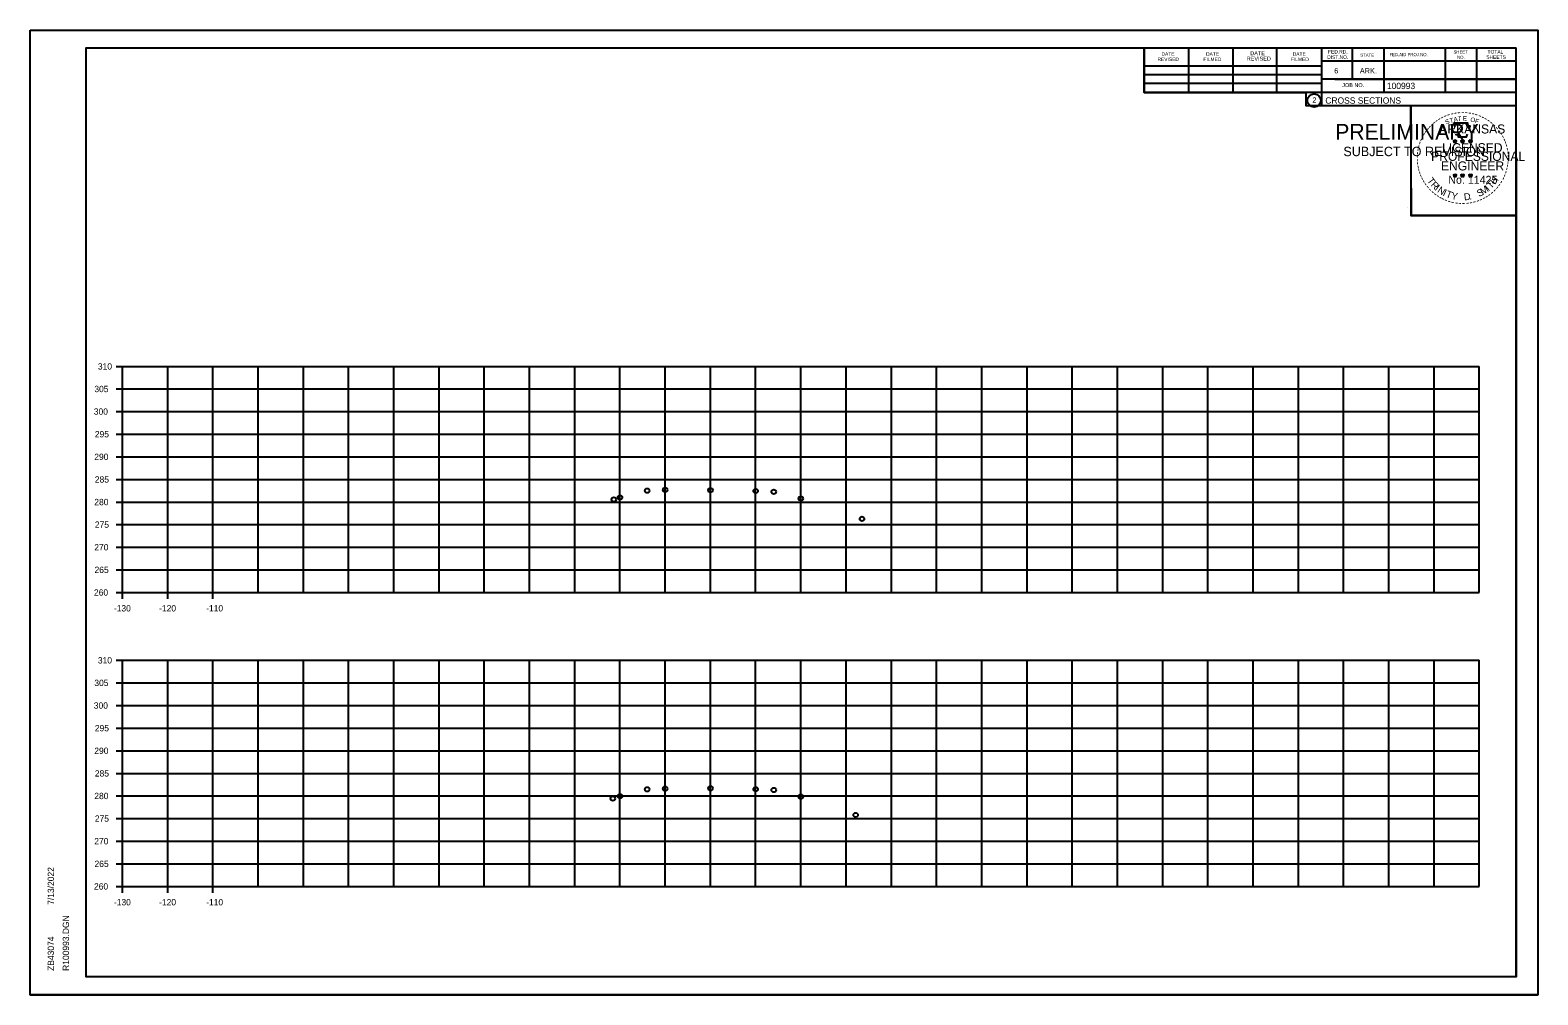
# Model space of a CAD drawing. Extents: x 4667 to 1632277, y -2100 to 724501.
# Drawn here: x 5969.1 to 6302.5, y -43.7 to 169.6 of the extents above; entities that cross this region are included whole.
import ezdxf

# ---------------------------------------------------------------- set-up
doc = ezdxf.new("R2010")
doc.units = 0
for name, color, linetype in [('R_Axis', 7, 'Continuous'), ('R_Axis Annot', 7, 'Continuous'), ('R_Grid', 7, 'Continuous'), ('R_No Plot', 7, 'Continuous')]:
    doc.layers.add(name, color=color, linetype=linetype)

msp = doc.modelspace()

# ---------------------------------------------------------------- linework, layer by layer
at = {"layer": 'R_Axis'}
for p, q in [((5988.12, 95.26), (5989.52, 95.26)), ((5989.52, 45.26), (5989.52, 95.26)), ((5988.12, 90.26), (5989.52, 90.26)), ((5988.12, 85.26), (5989.52, 85.26)), ((5988.12, 80.26), (5989.52, 80.26)), ((5988.12, 75.26), (5989.52, 75.26)), ((5988.12, 70.26), (5989.52, 70.26)), ((5988.12, 65.26), (5989.52, 65.26)), ((5988.12, 60.26), (5989.52, 60.26)), ((5988.12, 55.26), (5989.52, 55.26)), ((5988.12, 50.26), (5989.52, 50.26)), ((5988.12, 45.26), (5989.52, 45.26)), ((5989.52, 43.86), (5989.52, 45.26)), ((5999.52, 43.86), (5999.52, 45.26)), ((6009.52, 43.86), (6009.52, 45.26)), ((5988.12, 30.26), (5989.52, 30.26)), ((5989.52, -19.74), (5989.52, 30.26)), ((5988.12, 25.26), (5989.52, 25.26)), ((5988.12, 20.26), (5989.52, 20.26)), ((5988.12, 15.26), (5989.52, 15.26)), ((5988.12, 10.26), (5989.52, 10.26)), ((5988.12, 5.26), (5989.52, 5.26)), ((5988.12, 0.26), (5989.52, 0.26)), ((5988.12, -4.74), (5989.52, -4.74)), ((5988.12, -9.74), (5989.52, -9.74)), ((5988.12, -14.74), (5989.52, -14.74)), ((5988.12, -19.74), (5989.52, -19.74)), ((5989.52, -21.14), (5989.52, -19.74)), ((5999.52, -21.14), (5999.52, -19.74)), ((6009.52, -21.14), (6009.52, -19.74))]:
    msp.add_line(p, q, dxfattribs=at)
at = {"layer": 'R_Grid'}
for p, q in [((5989.52, 95.26), (6289.52, 95.26)), ((5989.52, 45.26), (5989.52, 95.26)), ((5999.52, 45.26), (5999.52, 95.26)), ((6009.52, 45.26), (6009.52, 95.26)), ((6019.52, 45.26), (6019.52, 95.26)), ((6029.52, 45.26), (6029.52, 95.26)), ((6039.52, 45.26), (6039.52, 95.26)), ((6049.52, 45.26), (6049.52, 95.26)), ((6059.52, 45.26), (6059.52, 95.26)), ((6069.52, 45.26), (6069.52, 95.26)), ((6079.52, 45.26), (6079.52, 95.26)), ((6089.52, 45.26), (6089.52, 95.26)), ((6099.52, 45.26), (6099.52, 95.26)), ((6109.52, 45.26), (6109.52, 95.26)), ((6119.52, 45.26), (6119.52, 95.26)), ((6129.52, 45.26), (6129.52, 95.26)), ((6139.52, 45.26), (6139.52, 95.26)), ((6149.52, 45.26), (6149.52, 95.26)), ((6159.52, 45.26), (6159.52, 95.26)), ((6169.52, 45.26), (6169.52, 95.26)), ((6179.52, 45.26), (6179.52, 95.26)), ((6189.52, 45.26), (6189.52, 95.26)), ((6199.52, 45.26), (6199.52, 95.26)), ((6209.52, 45.26), (6209.52, 95.26)), ((6219.52, 45.26), (6219.52, 95.26)), ((6229.52, 45.26), (6229.52, 95.26)), ((6239.52, 45.26), (6239.52, 95.26)), ((6249.52, 45.26), (6249.52, 95.26)), ((6259.52, 45.26), (6259.52, 95.26)), ((6269.52, 45.26), (6269.52, 95.26)), ((6279.52, 45.26), (6279.52, 95.26)), ((6289.52, 45.26), (6289.52, 95.26)), ((5989.52, 90.26), (6289.52, 90.26)), ((5989.52, 85.26), (6289.52, 85.26)), ((5989.52, 80.26), (6289.52, 80.26)), ((5989.52, 75.26), (6289.52, 75.26)), ((5989.52, 70.26), (6289.52, 70.26)), ((5989.52, 65.26), (6289.52, 65.26)), ((5989.52, 60.26), (6289.52, 60.26)), ((5989.52, 55.26), (6289.52, 55.26)), ((5989.52, 50.26), (6289.52, 50.26)), ((5989.52, 45.26), (6289.52, 45.26)), ((5989.52, 30.26), (6289.52, 30.26)), ((5989.52, -19.74), (5989.52, 30.26)), ((5999.52, -19.74), (5999.52, 30.26)), ((6009.52, -19.74), (6009.52, 30.26)), ((6019.52, -19.74), (6019.52, 30.26)), ((6029.52, -19.74), (6029.52, 30.26)), ((6039.52, -19.74), (6039.52, 30.26)), ((6049.52, -19.74), (6049.52, 30.26)), ((6059.52, -19.74), (6059.52, 30.26)), ((6069.52, -19.74), (6069.52, 30.26)), ((6079.52, -19.74), (6079.52, 30.26)), ((6089.52, -19.74), (6089.52, 30.26)), ((6099.52, -19.74), (6099.52, 30.26)), ((6109.52, -19.74), (6109.52, 30.26)), ((6119.52, -19.74), (6119.52, 30.26)), ((6129.52, -19.74), (6129.52, 30.26)), ((6139.52, -19.74), (6139.52, 30.26)), ((6149.52, -19.74), (6149.52, 30.26)), ((6159.52, -19.74), (6159.52, 30.26)), ((6169.52, -19.74), (6169.52, 30.26)), ((6179.52, -19.74), (6179.52, 30.26)), ((6189.52, -19.74), (6189.52, 30.26)), ((6199.52, -19.74), (6199.52, 30.26)), ((6209.52, -19.74), (6209.52, 30.26)), ((6219.52, -19.74), (6219.52, 30.26)), ((6229.52, -19.74), (6229.52, 30.26)), ((6239.52, -19.74), (6239.52, 30.26)), ((6249.52, -19.74), (6249.52, 30.26)), ((6259.52, -19.74), (6259.52, 30.26)), ((6269.52, -19.74), (6269.52, 30.26)), ((6279.52, -19.74), (6279.52, 30.26)), ((6289.52, -19.74), (6289.52, 30.26)), ((5989.52, 25.26), (6289.52, 25.26)), ((5989.52, 20.26), (6289.52, 20.26)), ((5989.52, 15.26), (6289.52, 15.26)), ((5989.52, 10.26), (6289.52, 10.26)), ((5989.52, 5.26), (6289.52, 5.26)), ((5989.52, 0.26), (6289.52, 0.26)), ((5989.52, -4.74), (6289.52, -4.74)), ((5989.52, -9.74), (6289.52, -9.74)), ((5989.52, -14.74), (6289.52, -14.74)), ((5989.52, -19.74), (6289.52, -19.74))]:
    msp.add_line(p, q, dxfattribs=at)
at = {"layer": 'R_No Plot'}
for p, q in [((5969.12, 169.61), (6302.46, 169.61)), ((5981.52, 165.72), (6297.7, 165.72)), ((5981.52, -39.74), (5981.52, 165.72)), ((6134.04, 165.46), (6134.04, 165.46)), ((6134.04, 165.46), (6134.04, 165.46)), ((6215.44, 155.84), (6215.44, 165.72)), ((6225.3, 155.84), (6225.3, 165.52)), ((6235.06, 155.84), (6235.06, 165.52)), ((6244.74, 155.84), (6244.74, 165.52)), ((6254.6, 165.72), (6254.6, 152.92)), ((6261.44, 165.72), (6261.44, 158.78)), ((6268.38, 165.72), (6268.38, 155.84)), ((6281.96, 165.72), (6281.96, 155.84)), ((6288.9, 165.72), (6288.9, 155.84)), ((6297.7, -39.74), (6297.7, 165.72)), ((6215.44, 161.7), (6254.6, 161.7)), ((6297.7, 162.78), (6254.6, 162.78)), ((6297.7, 162.8), (6297.7, 162.8)), ((6215.44, 159.84), (6254.6, 159.84)), ((6215.44, 155.84), (6215.44, 157.9)), ((6215.44, 157.9), (6254.6, 157.9)), ((6297.7, 158.78), (6254.6, 158.78)), ((6257.56, 158.78), (6297.7, 158.78)), ((6297.7, 155.84), (6215.44, 155.84)), ((6254.6, 152.92), (6297.7, 152.92)), ((6283.79, 145.17), (6284.14, 145.06)), ((6283.79, 145.17), (6284.04, 145.13)), ((6283.79, 145.17), (6284.03, 145.05)), ((6283.92, 144.77), (6284.14, 145.06)), ((6283.92, 144.77), (6284.05, 145.01)), ((6283.92, 144.77), (6284.14, 144.98)), ((6284.14, 145.43), (6284.1, 145.18)), ((6284.14, 145.06), (6284.14, 145.43)), ((6284.14, 145.43), (6284.19, 145.18)), ((6284.49, 145.17), (6284.14, 145.06)), ((6284.35, 144.77), (6284.14, 145.06)), ((6284.35, 144.77), (6284.14, 144.98)), ((6284.49, 145.17), (6284.2, 145.13)), ((6284.35, 144.77), (6284.21, 145.06)), ((6284.49, 145.17), (6284.28, 145.07)), ((6285.46, 145.17), (6285.81, 145.06)), ((6285.46, 145.17), (6285.71, 145.13)), ((6285.46, 145.17), (6285.7, 145.05)), ((6285.59, 144.77), (6285.81, 145.06)), ((6285.59, 144.77), (6285.72, 145.01)), ((6285.59, 144.77), (6285.81, 144.98)), ((6285.81, 145.43), (6285.77, 145.18)), ((6285.81, 145.06), (6285.81, 145.43)), ((6285.81, 145.43), (6285.86, 145.18)), ((6286.16, 145.17), (6285.81, 145.06)), ((6286.02, 144.77), (6285.81, 145.06)), ((6286.02, 144.77), (6285.81, 144.98)), ((6286.16, 145.17), (6285.87, 145.13)), ((6286.02, 144.77), (6285.88, 145.06)), ((6286.16, 145.17), (6285.95, 145.07)), ((6287.22, 145.16), (6287.57, 145.05)), ((6287.22, 145.16), (6287.48, 145.12)), ((6287.22, 145.16), (6287.46, 145.04)), ((6287.36, 144.75), (6287.57, 145.05)), ((6287.36, 144.75), (6287.48, 145)), ((6287.36, 144.75), (6287.57, 144.97)), ((6287.57, 145.42), (6287.53, 145.16)), ((6287.57, 145.05), (6287.57, 145.42)), ((6287.57, 145.42), (6287.62, 145.17)), ((6287.92, 145.16), (6287.57, 145.05)), ((6287.79, 144.75), (6287.57, 145.05)), ((6287.79, 144.75), (6287.57, 144.97)), ((6287.92, 145.16), (6287.63, 145.11)), ((6287.79, 144.75), (6287.65, 145.05)), ((6287.92, 145.16), (6287.72, 145.06)), ((6283.79, 137.6), (6284.13, 137.49)), ((6283.79, 137.6), (6284.04, 137.56)), ((6283.79, 137.6), (6284.02, 137.48)), ((6283.92, 137.19), (6284.13, 137.49)), ((6283.92, 137.19), (6284.04, 137.44)), ((6283.92, 137.19), (6284.13, 137.41)), ((6284.13, 137.86), (6284.09, 137.6)), ((6284.13, 137.49), (6284.13, 137.86)), ((6284.13, 137.86), (6284.18, 137.61)), ((6284.48, 137.6), (6284.13, 137.49)), ((6284.35, 137.19), (6284.13, 137.49)), ((6284.35, 137.19), (6284.13, 137.41)), ((6284.48, 137.6), (6284.2, 137.55)), ((6284.35, 137.19), (6284.21, 137.48)), ((6284.48, 137.6), (6284.28, 137.5)), ((6285.45, 137.6), (6285.8, 137.49)), ((6285.45, 137.6), (6285.71, 137.56)), ((6285.45, 137.6), (6285.69, 137.48)), ((6285.59, 137.19), (6285.8, 137.49)), ((6285.59, 137.19), (6285.71, 137.44)), ((6285.59, 137.19), (6285.8, 137.41)), ((6285.8, 137.86), (6285.76, 137.6)), ((6285.8, 137.49), (6285.8, 137.86)), ((6285.8, 137.86), (6285.85, 137.61)), ((6286.15, 137.6), (6285.8, 137.49)), ((6286.02, 137.19), (6285.8, 137.49)), ((6286.02, 137.19), (6285.8, 137.41)), ((6286.15, 137.6), (6285.86, 137.55)), ((6286.02, 137.19), (6285.88, 137.48)), ((6286.15, 137.6), (6285.95, 137.5)), ((6287.22, 137.59), (6287.57, 137.48)), ((6287.22, 137.59), (6287.47, 137.55)), ((6287.22, 137.59), (6287.46, 137.47)), ((6287.35, 137.18), (6287.57, 137.48)), ((6287.35, 137.18), (6287.48, 137.43)), ((6287.35, 137.18), (6287.57, 137.4)), ((6287.57, 137.85), (6287.53, 137.59)), ((6287.57, 137.48), (6287.57, 137.85)), ((6287.57, 137.85), (6287.62, 137.6)), ((6287.92, 137.59), (6287.57, 137.48)), ((6287.78, 137.18), (6287.57, 137.48)), ((6287.78, 137.18), (6287.57, 137.4)), ((6287.92, 137.59), (6287.63, 137.54)), ((6287.78, 137.18), (6287.65, 137.47)), ((6287.92, 137.59), (6287.71, 137.49)), ((6273.74, 130.46), (6273.74, 130.46)), ((5981.52, -39.74), (5981.52, -39.74)), ((6297.7, -39.74), (5981.52, -39.74)), ((5969.12, -43.72), (6302.46, -43.72))]:
    msp.add_line(p, q, dxfattribs=at)
for points in [[(5969.12, 169.61), (6302.46, 169.61), (6302.46, -43.72), (5969.12, -43.72)], [(6215.44, 165.72), (6215.44, 155.84), (6251.18, 155.84), (6251.18, 152.92), (6274.38, 152.92), (6274.38, 128.59), (6297.7, 128.59), (6297.7, -39.74), (5981.52, -39.74), (5981.52, 165.72)], [(6274.38, 152.92), (6297.58, 152.92), (6297.7, 128.59), (6274.5, 128.59)]]:
    msp.add_lwpolyline(points, close=True, dxfattribs=at)
for points in [[(6283.83, 149.05), (6284.1, 148.23)], [(6287.34, 148.13), (6287.48, 148.41), (6286.8, 148.39), (6286.95, 149.05), (6283.83, 149.05)], [(6284.14, 145.43), (6284.35, 144.77), (6283.79, 145.17), (6284.49, 145.17), (6283.92, 144.77), (6284.14, 145.43)], [(6284.32, 146.63), (6284.32, 146.54), (6284.89, 146.52), (6284.83, 146.05), (6286.7, 146.05), (6286.9, 146.59)], [(6285.81, 145.43), (6286.02, 144.77), (6285.46, 145.17), (6286.16, 145.17), (6285.59, 144.77), (6285.81, 145.43)], [(6287.57, 145.42), (6287.79, 144.75), (6287.22, 145.16), (6287.92, 145.16), (6287.36, 144.75), (6287.57, 145.42)], [(6284.13, 137.86), (6284.35, 137.19), (6283.79, 137.6), (6284.48, 137.6), (6283.92, 137.19), (6284.13, 137.86)], [(6285.8, 137.86), (6286.02, 137.19), (6285.45, 137.6), (6286.15, 137.6), (6285.59, 137.19), (6285.8, 137.86)], [(6287.57, 137.85), (6287.78, 137.18), (6287.22, 137.59), (6287.92, 137.59), (6287.35, 137.18), (6287.57, 137.85)]]:
    msp.add_lwpolyline(points, dxfattribs=at)
for centre, radius in [((6252.99, 154.06), 1.47), ((6284.14, 145.06), 0.172), ((6284.14, 145.06), 0.145), ((6284.14, 145.06), 0.116), ((6284.14, 145.06), 0.0991), ((6284.14, 145.06), 0.0747), ((6284.14, 145.06), 0.0495), ((6284.14, 145.06), 0.0296), ((6285.81, 145.06), 0.172), ((6285.81, 145.06), 0.145), ((6285.81, 145.06), 0.116), ((6285.81, 145.06), 0.0991), ((6285.81, 145.06), 0.0747), ((6285.81, 145.06), 0.0495), ((6285.81, 145.06), 0.0296), ((6287.57, 145.05), 0.172), ((6287.57, 145.05), 0.145), ((6287.57, 145.05), 0.116), ((6287.57, 145.05), 0.0991), ((6287.57, 145.05), 0.0747), ((6287.57, 145.05), 0.0495), ((6287.57, 145.05), 0.0296), ((6284.13, 137.49), 0.172), ((6284.13, 137.49), 0.145), ((6284.13, 137.49), 0.116), ((6284.13, 137.49), 0.0991), ((6284.13, 137.49), 0.0747), ((6284.13, 137.49), 0.0495), ((6284.13, 137.49), 0.0296), ((6285.8, 137.49), 0.172), ((6285.8, 137.49), 0.145), ((6285.8, 137.49), 0.116), ((6285.8, 137.49), 0.0991), ((6285.8, 137.49), 0.0747), ((6285.8, 137.49), 0.0495), ((6285.8, 137.49), 0.0296), ((6287.57, 137.48), 0.172), ((6287.57, 137.48), 0.145), ((6287.57, 137.48), 0.116), ((6287.57, 137.48), 0.0991), ((6287.57, 137.48), 0.0747), ((6287.57, 137.48), 0.0495), ((6287.57, 137.48), 0.0296), ((6099.52, 66.28), 0.5), ((6105.52, 67.78), 0.5), ((6109.52, 67.94), 0.5), ((6119.52, 67.89), 0.5), ((6129.52, 67.69), 0.5), ((6133.52, 67.53), 0.5), ((6098.17, 65.83), 0.5), ((6139.52, 66.03), 0.5), ((6153.02, 61.53), 0.5), ((6097.95, -0.3), 0.5), ((6099.52, 0.22), 0.5), ((6105.52, 1.72), 0.5), ((6109.52, 1.88), 0.5), ((6119.52, 1.95), 0.5), ((6129.52, 1.75), 0.5), ((6133.52, 1.59), 0.5), ((6139.52, 0.09), 0.5), ((6151.62, -3.95), 0.5)]:
    msp.add_circle(centre, radius, dxfattribs=at)

# ---------------------------------------------------------------- texts
at = {"layer": 'R_Axis Annot'}
for s, p in [('310', (5984.09, 94.56)), ('305', (5983.31, 89.56)), ('300', (5983.19, 84.56)), ('295', (5983.42, 79.56)), ('290', (5983.3, 74.56)), ('285', (5983.42, 69.56)), ('280', (5983.3, 64.56)), ('275', (5983.42, 59.56)), ('270', (5983.3, 54.56)), ('265', (5983.35, 49.56)), ('260', (5983.23, 44.56)), ('-130', (5987.63, 41.06)), ('-120', (5997.63, 41.06)), ('-110', (6008.03, 41.06)), ('310', (5984.09, 29.56)), ('305', (5983.31, 24.56)), ('300', (5983.19, 19.56)), ('295', (5983.42, 14.56)), ('290', (5983.3, 9.56)), ('285', (5983.42, 4.56)), ('280', (5983.3, -0.44)), ('275', (5983.42, -5.44)), ('270', (5983.3, -10.44)), ('265', (5983.35, -15.44)), ('260', (5983.23, -20.44)), ('-130', (5987.63, -23.94)), ('-120', (5997.63, -23.94)), ('-110', (6008.03, -23.94))]:
    msp.add_text(s, height=1.4, dxfattribs=at).set_placement(p)
at = {"layer": 'R_No Plot'}
for s, height, rotation, p in [('REVISED', 0.782, 360, (6218.36, 162.78)), ('DATE', 0.782, 360, (6219.24, 163.96)), ('FILMED', 0.782, 360, (6228.52, 162.78)), ('DATE', 0.782, 360, (6229.1, 163.96)), ('REVISED', 0.879, 360, (6238.1, 162.88)), ('DATE', 0.879, 360, (6238.88, 164.06)), ('FILMED', 0.782, 360, (6247.86, 162.78)), ('DATE', 0.782, 360, (6248.26, 163.96)), ('DIST.NO.', 0.782, 360, (6255.88, 163.26)), ('FED.RD.', 0.782, 360, (6256.08, 164.44)), ('STATE', 0.684, 360, (6263.2, 163.76)), ('FED.AID PROJ.NO.', 0.684, 360, (6269.66, 163.86)), ('SHEET', 0.684, 360, (6283.82, 164.44)), ('NO.', 0.684, 360, (6284.6, 163.26)), ('SHEETS', 0.782, 360, (6291.06, 163.26)), ('TOTAL', 0.782, 360, (6291.34, 164.44)), ('6', 1.17, 360, (6257.44, 160.04)), ('ARK.', 1.172, 360, (6263.1, 160.04)), ('JOB NO.', 0.879, 360, (6259.2, 157.02)), ('100993', 1.4, 360, (6269.08, 156.58)), ('2', 1.17, 360, (6252.61, 153.57)), ('CROSS SECTIONS', 1.4, 360, (6255.47, 153.35)), ('-', 1.6, 34.0636, (6280.71, 149.22)), ('-', 1.6, 28.7918, (6281.31, 149.59)), ('-', 1.6, 24.3072, (6281.94, 149.91)), ('-', 1.6, 19.1761, (6282.58, 150.18)), ('T', 1, 16.4036, (6283.1, 149.06)), ('-', 1.6, 13.6301, (6283.33, 150.42)), ('A', 1, 11.2132, (6283.92, 149.31)), ('-', 1.6, 10.2193, (6284.01, 150.58)), ('T', 1, 6.0228, (6284.77, 149.48)), ('-', 1.6, 5.8968, (6284.73, 150.69)), ('-', 1.6, 0.1862, (6285.51, 150.76)), ('E', 1, 0.8323, (6285.88, 149.59)), ('-', 1.6, 357.743, (6286.23, 150.75)), ('-', 1.6, 352.1617, (6286.97, 150.7)), ('O', 1, 350.4515, (6287.48, 149.38)), ('-', 1.6, 347.2049, (6287.69, 150.58)), ('F', 1, 340.0707, (6288.44, 149.15)), ('-', 1.6, 342.3362, (6288.33, 150.43)), ('-', 1.6, 337.8551, (6289.06, 150.2)), ('-', 1.6, 334.1211, (6289.69, 149.93)), ('-', 1.6, 329.6409, (6290.27, 149.65)), ('PRELIMINARY', 3.5, 360, (6257.66, 145.38)), ('DWB', 0.01, 360, (6258.4, 147.23)), ('-', 1.6, 58.0706, (6277.64, 145.98)), ('-', 1.6, 54.2325, (6277.96, 146.5)), ('-', 1.6, 50.6142, (6278.38, 147.07)), ('-', 1.6, 48.423, (6278.78, 147.56)), ('-', 1.6, 42.9622, (6279.23, 148.03)), ('-', 1.6, 38.9507, (6279.66, 148.45)), ('-', 1.6, 36.2317, (6280.14, 148.83)), ('ARKANSAS', 2, 360, (6280.68, 146.76)), ('S', 1, 21.594, (6282.18, 148.73)), ('-', 1.6, 325.8627, (6290.92, 149.29)), ('-', 1.6, 320.5297, (6291.53, 148.86)), ('-', 1.6, 315.5786, (6292.12, 148.37)), ('-', 1.6, 309.8797, (6292.69, 147.82)), ('-', 1.6, 306.6522, (6293.22, 147.22)), ('-', 1.4, 303.6753, (6293.7, 146.65)), ('SUBJECT TO REVISION', 2.0751, 360, (6259.46, 141.75)), ('-', 1.6, 81.2013, (6276.52, 142.69)), ('-', 1.6, 75.461, (6276.65, 143.41)), ('-', 1.6, 72.3945, (6276.85, 144.12)), ('-', 1.6, 67.7743, (6277.07, 144.75)), ('-', 1.6, 62.8713, (6277.32, 145.36)), ('LICENSED', 2, 360, (6281.28, 142.62)), ('DWB', 0.01, 360, (6284.13, 145.06)), ('DWB', 0.01, 360, (6285.8, 145.06)), ('DWB', 0.01, 360, (6287.56, 145.05)), ('-', 1.6, 299.6684, (6294.02, 146.05)), ('-', 1.6, 294.6628, (6294.35, 145.44)), ('-', 1.6, 290.5728, (6294.6, 144.86)), ('-', 1.6, 285.1233, (6294.84, 144.28)), ('-', 1.6, 280.5493, (6295.04, 143.54)), ('-', 1.6, 94.1959, (6276.45, 140.58)), ('-', 1.6, 89.0622, (6276.42, 141.3)), ('-', 1.6, 98.9479, (6276.52, 139.91)), ('-', 1.6, 85.1863, (6276.44, 142)), ('PROFESSIONAL', 2, 360, (6278.86, 140.71)), ('ENGINEER', 2, 360, (6281.04, 138.59)), ('-', 1.6, 263.5172, (6295.28, 140.75)), ('-', 1.6, 276.5962, (6295.2, 142.77)), ('-', 1.6, 274.3301, (6295.26, 142.05)), ('-', 1.6, 269.9407, (6295.29, 141.41)), ('-', 1.6, 101.7149, (6276.66, 139.18)), ('-', 1.6, 105.4578, (6276.82, 138.58)), ('-', 1.6, 109.0874, (6277.04, 137.95)), ('-', 1.6, 114.0643, (6277.29, 137.35)), ('-', 1.6, 115.7289, (6277.59, 136.74)), ('T', 1.54, 306.0406, (6277.89, 136.33)), ('No. 11425', 1.757, 360, (6282.67, 135.64)), ('DWB', 0.01, 360, (6284.12, 137.49)), ('DWB', 0.01, 360, (6285.79, 137.49)), ('DWB', 0.01, 360, (6287.56, 137.48)), ('H', 1.54, 54.6088, (6293.01, 135.36)), ('-', 1.6, 244.6197, (6294.43, 137.39)), ('-', 1.6, 247.8887, (6294.69, 138.02)), ('-', 1.6, 252.8681, (6294.91, 138.7)), ('-', 1.6, 255.7626, (6295.09, 139.42)), ('-', 1.6, 260.9953, (6295.2, 140.09)), ('-', 1.6, 120.4471, (6277.95, 136.15)), ('-', 1.6, 125.8934, (6278.35, 135.59)), ('-', 1.6, 130.7181, (6278.82, 135.04)), ('-', 1.6, 134.2238, (6279.33, 134.49)), ('R', 1.54, 314.005, (6278.66, 135.28)), ('-', 1.6, 138.9338, (6279.86, 134.03)), ('-', 1.6, 144.6463, (6280.41, 133.62)), ('I', 1.54, 321.9694, (6279.56, 134.35)), ('N', 1.54, 326.5002, (6280.12, 133.88)), ('I', 1.54, 335.3603, (6281.33, 133.09)), ('T', 1.54, 339.8912, (6281.99, 132.76)), ('Y', 1.54, 347.8556, (6283.21, 132.32)), ('D', 1.54, 6.3969, (6286.19, 131.96)), ('S', 1.54, 26.9312, (6289.44, 132.69)), ('M', 1.54, 32.6563, (6290.28, 133.1)), ('I', 1.54, 42.1136, (6291.56, 133.94)), ('T', 1.54, 46.6444, (6292.12, 134.42)), ('-', 1.6, 215.7363, (6291.65, 133.88)), ('-', 1.6, 221.0851, (6292.2, 134.35)), ('-', 1.6, 225.7653, (6292.72, 134.86)), ('-', 1.6, 231.2538, (6293.2, 135.42)), ('-', 1.6, 233.8452, (6293.63, 135.99)), ('-', 1.6, 239.0712, (6294.03, 136.64)), ('-', 1.6, 148.0898, (6280.98, 133.25)), ('-', 1.6, 151.5704, (6281.55, 132.93)), ('-', 1.6, 154.6002, (6282.08, 132.68)), ('-', 1.6, 158.5612, (6282.7, 132.43)), ('-', 1.6, 162.7983, (6283.39, 132.21)), ('-', 1.6, 167.5555, (6284.1, 132.05)), ('-', 1.6, 173.1155, (6284.87, 131.94)), ('-', 1.6, 176.5183, (6285.62, 131.89)), ('-', 1.6, 181.5918, (6286.37, 131.9)), ('-', 1.6, 185.8167, (6287.18, 131.98)), ('-', 1.6, 191.2858, (6287.91, 132.11)), ('.', 1.54, 13.7642, (6287.39, 132.09)), ('-', 1.6, 195.4743, (6288.64, 132.31)), ('-', 1.6, 200.7184, (6289.32, 132.55)), ('-', 1.6, 204.2516, (6289.94, 132.83)), ('-', 1.6, 207.3568, (6290.56, 133.15)), ('-', 1.6, 212.2491, (6291.12, 133.49)), ('7/13/2022', 1.4, 90, (5974.39, -23.81)), ('R100993.DGN', 1.4, 90, (5977.72, -38.42)), ('ZB43074', 1.4, 90, (5974.39, -38.42))]:
    msp.add_text(s, height=height, rotation=rotation, dxfattribs=at).set_placement(p)

doc.saveas('drawing.dxf')
